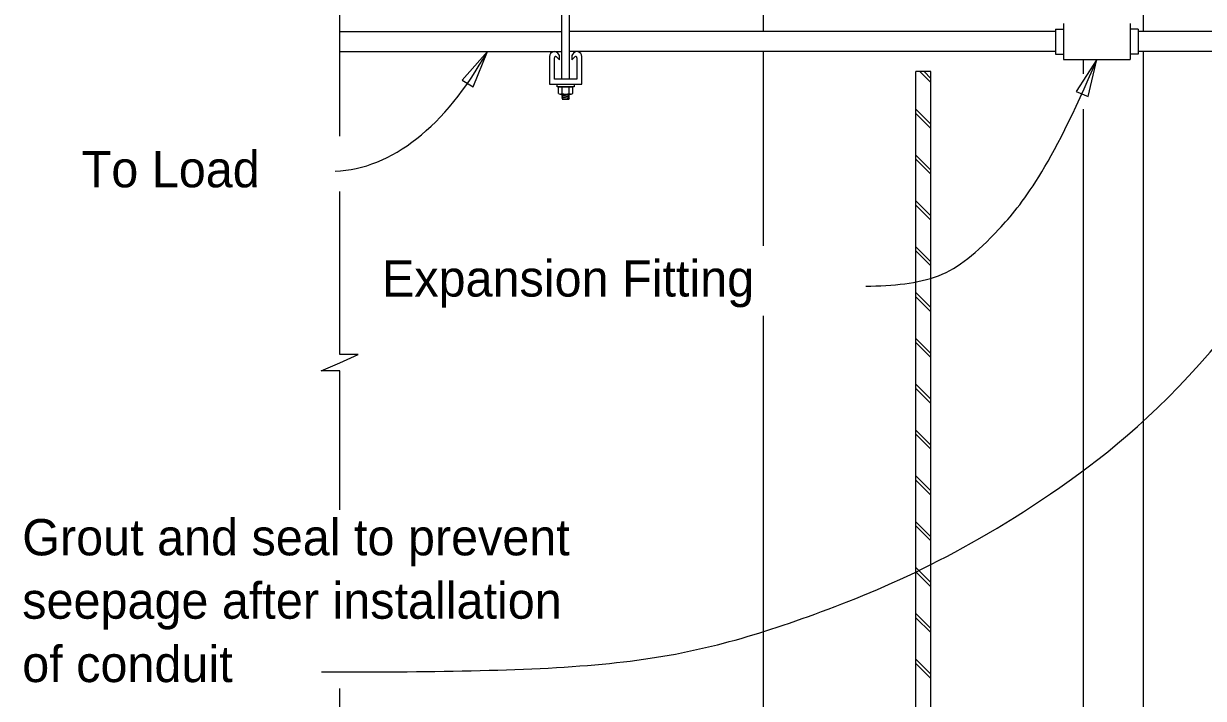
# Model space of a CAD drawing. Extents: x 112544 to 112597.1, y 111084 to 111107.1.
# Drawn here: x 112565.33 to 112570.246, y 111089.924 to 111092.735 of the extents above; entities that cross this region are included whole.
import ezdxf

# ---------------------------------------------------------------- set-up
doc = ezdxf.new("R2010")
doc.units = 0
for name, color, linetype in [('Dimension', 7, 'Continuous'), ('Lighting', 7, 'Continuous'), ('Miscellaneous', 7, 'Continuous'), ('SteelGirder', 7, 'Continuous'), ('TextStructures', 7, 'Continuous')]:
    doc.layers.add(name, color=color, linetype=linetype)

msp = doc.modelspace()

# ---------------------------------------------------------------- linework, layer by layer
at = {"layer": 'Dimension'}
for points in [[(112566.6473, 111092.2662), (112566.6473, 111094.5328)], [(112566.6473, 111090.71), (112566.6473, 111091.289), (112566.5698, 111091.289), (112566.6473, 111091.3227), (112566.7248, 111091.3565), (112566.6473, 111091.3565), (112566.6473, 111092.0355)], [(112566.6473, 111089.6865), (112566.6473, 111089.9653)]]:
    msp.add_lwpolyline(points, dxfattribs=at)
for points in [[(112567.2626, 111092.6186), (112567.1581, 111092.4995), (112567.2032, 111092.4718)], [(112569.8022, 111092.5853), (112569.7168, 111092.4519), (112569.7655, 111092.4312)]]:
    msp.add_lwpolyline(points, close=True, dxfattribs=at)
msp.add_ellipse((112566.5174, 111094.4874), major_axis=(-0.1111, 2.3674), ratio=0.464296, start_param=3.141604, end_param=3.781059, dxfattribs=at)
for points in [[(112568.8393, 111091.6417), (112568.9548, 111091.6436), (112569.157, 111091.6596), (112569.3709, 111091.8371), (112569.6073, 111092.124), (112569.8022, 111092.5853)], [(112566.5718, 111090.0345), (112566.9987, 111090.0346), (112567.8381, 111090.0387), (112568.5158, 111090.2156), (112569.5419, 111090.6383), (112570.4976, 111091.4736), (112571.0308, 111092.5697)]]:
    msp.add_open_spline(points, degree=3, dxfattribs=at)
at = {"layer": 'Lighting'}
for p, q in [((112569.6635, 111092.7352), (112569.6635, 111092.5853)), ((112569.941, 111092.7351), (112569.941, 111092.5852)), ((112566.6473, 111092.7018), (112567.5731, 111092.7018)), ((112569.6301, 111092.7018), (112567.6043, 111092.7018)), ((112569.6301, 111092.7121), (112569.6301, 111092.608)), ((112569.6301, 111092.7121), (112569.6635, 111092.7121)), ((112569.9743, 111092.7121), (112569.9409, 111092.7121)), ((112569.9743, 111092.7121), (112569.9743, 111092.608)), ((112573.0332, 111092.7019), (112569.9743, 111092.7019)), ((112566.6473, 111092.6185), (112567.5731, 111092.6185)), ((112567.521, 111092.5977), (112567.521, 111092.4831)), ((112567.5418, 111092.5039), (112567.5418, 111092.5929)), ((112567.5506, 111092.5966), (112567.5626, 111092.5847)), ((112567.5626, 111092.6026), (112567.5604, 111092.6069)), ((112567.5626, 111092.5847), (112567.5626, 111092.6026)), ((112569.6301, 111092.6185), (112567.6043, 111092.6185)), ((112567.6169, 111092.6069), (112567.6148, 111092.6026)), ((112567.6148, 111092.6026), (112567.6148, 111092.5847)), ((112567.6148, 111092.5847), (112567.6267, 111092.5966)), ((112567.6356, 111092.5929), (112567.6356, 111092.5039)), ((112567.6564, 111092.4831), (112567.6564, 111092.5977)), ((112569.6301, 111092.608), (112569.6635, 111092.608)), ((112569.6635, 111092.5853), (112569.9409, 111092.5853)), ((112569.9743, 111092.608), (112569.9409, 111092.608)), ((112573.0332, 111092.6186), (112569.9743, 111092.6186)), ((112567.521, 111092.4831), (112567.6564, 111092.4831)), ((112567.6356, 111092.5039), (112567.5418, 111092.5039))]:
    msp.add_line(p, q, dxfattribs=at)
for centre, radius, start, end in [((112567.5418, 111092.5977), 0.0208, 26.1794, 179.9999), ((112567.547, 111092.5929), 0.0052, 45, 180), ((112567.6356, 111092.5977), 0.0208, 0.0001, 153.8206), ((112567.6304, 111092.5929), 0.0052, 360, 135)]:
    msp.add_arc(centre, radius, start, end, dxfattribs=at)
at = {"layer": 'Miscellaneous'}
for p, q in [((112569.1109, 111092.4893), (112569.065, 111092.5352)), ((112569.1109, 111092.507), (112569.0826, 111092.5352)), ((112569.1109, 111092.316), (112569.0485, 111092.3784)), ((112569.1109, 111092.2984), (112569.0485, 111092.3608)), ((112569.1109, 111092.1251), (112569.0485, 111092.1875)), ((112569.1109, 111092.1074), (112569.0485, 111092.1698)), ((112569.1109, 111091.9342), (112569.0485, 111091.9966)), ((112569.1109, 111091.9165), (112569.0485, 111091.9789)), ((112569.1109, 111091.7433), (112569.0485, 111091.8057)), ((112569.1109, 111091.7256), (112569.0485, 111091.788)), ((112569.1109, 111091.5524), (112569.0485, 111091.6148)), ((112569.1109, 111091.5347), (112569.0485, 111091.5971)), ((112569.1109, 111091.3614), (112569.0485, 111091.4238)), ((112569.1109, 111091.3438), (112569.0485, 111091.4062)), ((112569.1109, 111091.1705), (112569.0485, 111091.2329)), ((112569.1109, 111091.1528), (112569.0485, 111091.2152)), ((112569.1109, 111090.9796), (112569.0485, 111091.042)), ((112569.1109, 111090.9619), (112569.0485, 111091.0243)), ((112569.1109, 111090.7887), (112569.0485, 111090.8511)), ((112569.1109, 111090.771), (112569.0485, 111090.8334)), ((112569.1109, 111090.5978), (112569.0485, 111090.6602)), ((112569.1109, 111090.5801), (112569.0485, 111090.6425)), ((112569.1109, 111090.4069), (112569.0485, 111090.4692)), ((112569.1109, 111090.3892), (112569.0485, 111090.4516)), ((112569.1109, 111090.2159), (112569.0485, 111090.2783)), ((112569.1109, 111090.1983), (112569.0485, 111090.2606)), ((112569.1109, 111090.025), (112569.0485, 111090.0874)), ((112569.1109, 111090.0073), (112569.0485, 111090.0697))]:
    msp.add_line(p, q, dxfattribs=at)
at = {"layer": 'SteelGirder'}
for p, q in [((112567.5731, 111092.5039), (112567.5731, 111093.5642)), ((112567.6043, 111092.5039), (112567.6043, 111093.5642)), ((112569.9964, 111092.7019), (112569.9964, 111093.4312)), ((112568.413, 111092.7018), (112568.413, 111093.408)), ((112568.413, 111091.8095), (112568.413, 111092.6185)), ((112569.7464, 111092.5265), (112569.7464, 111092.5853)), ((112569.9964, 111088.1504), (112569.9964, 111092.6186)), ((112569.0485, 111088.1504), (112569.0485, 111092.5352)), ((112569.1109, 111092.5352), (112569.0485, 111092.5352)), ((112569.1109, 111088.1504), (112569.1109, 111092.5352)), ((112567.5586, 111092.4436), (112567.5586, 111092.472)), ((112567.5586, 111092.472), (112567.6187, 111092.472)), ((112567.5661, 111092.4414), (112567.6112, 111092.4414)), ((112567.573, 111092.4408), (112567.5796, 111092.4414)), ((112567.573, 111092.4408), (112567.574, 111092.4414)), ((112567.5782, 111092.4386), (112567.573, 111092.4408)), ((112567.573, 111092.4356), (112567.5782, 111092.4386)), ((112567.573, 111092.4356), (112567.6042, 111092.4383)), ((112567.5782, 111092.4334), (112567.573, 111092.4356)), ((112567.573, 111092.4305), (112567.5782, 111092.4334)), ((112567.573, 111092.4305), (112567.6042, 111092.4331)), ((112567.5782, 111092.4283), (112567.573, 111092.4305)), ((112567.573, 111092.4253), (112567.5782, 111092.4283)), ((112567.5736, 111092.4436), (112567.5736, 111092.472)), ((112567.599, 111092.4405), (112567.6006, 111092.4414)), ((112567.6042, 111092.4383), (112567.599, 111092.4405)), ((112567.599, 111092.4353), (112567.6042, 111092.4383)), ((112567.6042, 111092.4331), (112567.599, 111092.4353)), ((112567.599, 111092.4301), (112567.6042, 111092.4331)), ((112567.6042, 111092.428), (112567.599, 111092.4301)), ((112567.6037, 111092.4436), (112567.6037, 111092.472)), ((112567.6187, 111092.4436), (112567.6187, 111092.472)), ((112567.573, 111092.4253), (112567.6042, 111092.428)), ((112567.5782, 111092.4231), (112567.573, 111092.4253)), ((112567.5748, 111092.4211), (112567.5782, 111092.4231)), ((112567.5748, 111092.4211), (112567.6014, 111092.4211)), ((112567.5849, 111092.4211), (112567.6042, 111092.4228)), ((112567.599, 111092.4249), (112567.6042, 111092.428)), ((112567.6042, 111092.4228), (112567.599, 111092.4249)), ((112567.6014, 111092.4211), (112567.6042, 111092.4228)), ((112569.7464, 111088.1504), (112569.7464, 111092.3781)), ((112568.413, 111088.1504), (112568.413, 111091.5176))]:
    msp.add_line(p, q, dxfattribs=at)
msp.add_lwpolyline([(112567.6239, 111092.4831), (112567.6239, 111092.472), (112567.5534, 111092.472), (112567.5534, 111092.4831)], close=True, dxfattribs=at)
for centre, radius, start, end in [((112567.5661, 111092.4552), 0.0138, 236.9791, 303.0209), ((112567.5886, 111092.4933), 0.0519, 253.1396, 286.8604), ((112567.6112, 111092.4552), 0.0138, 236.9791, 303.0209)]:
    msp.add_arc(centre, radius, start, end, dxfattribs=at)

# ---------------------------------------------------------------- texts
at = {"layer": 'Dimension'}
for s, p in [('Grout and seal to prevent ', (112565.3244, 111090.5202)), ('seepage after installation ', (112565.3244, 111090.2562)), ('of conduit', (112565.3244, 111089.9922))]:
    msp.add_text(s, height=0.1512, dxfattribs=at).set_placement(p)
at = {"layer": 'TextStructures'}
for s, p in [('To Load', (112565.5721, 111092.0533)), ('Expansion Fitting', (112566.8234, 111091.5982))]:
    msp.add_text(s, height=0.1512, dxfattribs=at).set_placement(p)

doc.saveas('drawing.dxf')
